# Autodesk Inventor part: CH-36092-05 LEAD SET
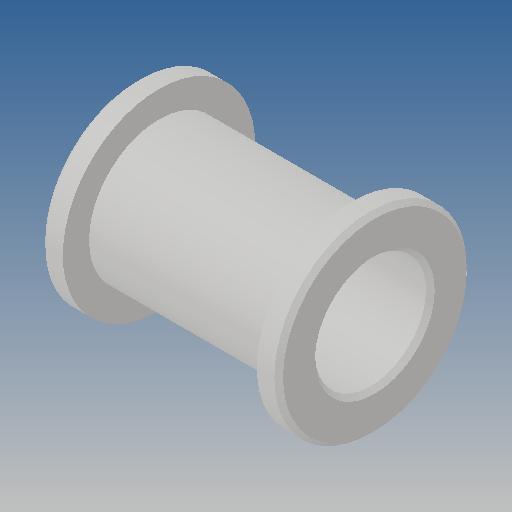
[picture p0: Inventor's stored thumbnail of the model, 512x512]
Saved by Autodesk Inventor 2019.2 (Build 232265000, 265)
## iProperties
Created: 2012-09
Part Number: CH-36092-05 LEAD SET
Material: Ogólny
Document SubType Name: Modeling
Designer: CADENGINEERING4
Density: 1 g/cm^3
Appearance: Domyślna
Author: CADENGINEERING4
Revision Number: ÈÎºÎ
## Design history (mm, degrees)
feature "µ¹½Ç1"
node "Bryła1"
